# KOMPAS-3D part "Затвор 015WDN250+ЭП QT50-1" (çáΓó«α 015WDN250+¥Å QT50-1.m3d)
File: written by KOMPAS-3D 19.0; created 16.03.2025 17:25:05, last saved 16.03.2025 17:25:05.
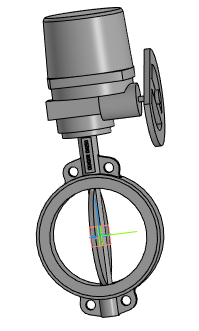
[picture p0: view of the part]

Document properties: Полное имя файла: Затвор 015WDN250+ЭП QT50-1.a3d

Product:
- Part/product: Затвор 015WDN250+ЭП QT50-1
    Масса: 105.77

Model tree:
1. Операция без истории:1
